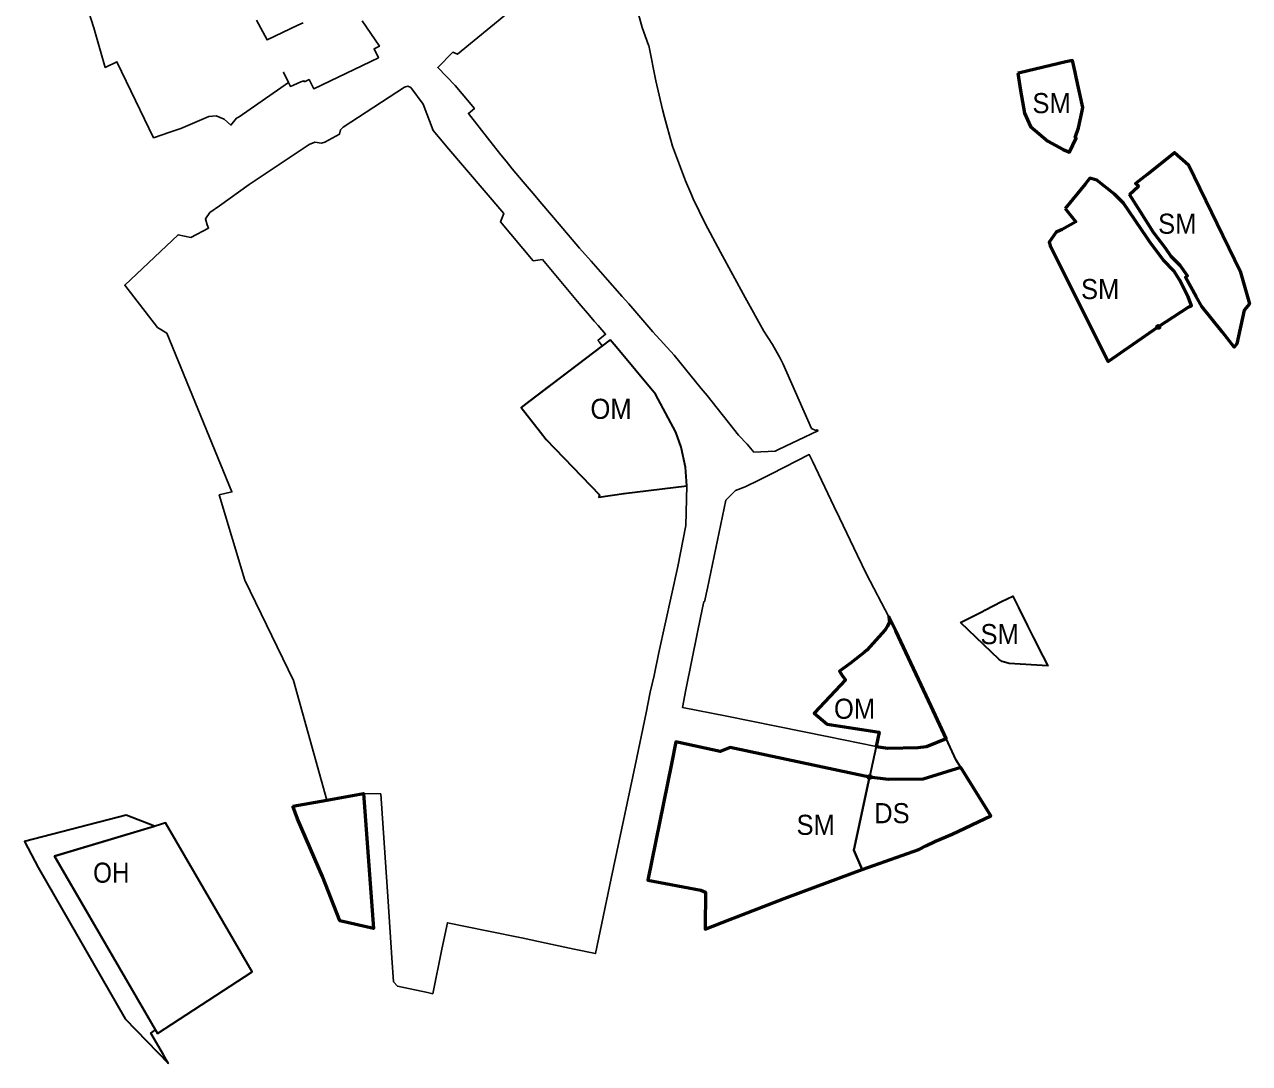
# Model space of a CAD drawing. Extents: x -650276 to -642489, y -1074311 to -1066720.
# Drawn here: x -647576 to -646845, y -1071614 to -1070993 of the extents above; entities that cross this region are included whole.
import ezdxf

# ---------------------------------------------------------------- set-up
doc = ezdxf.new("R2010")
doc.units = 0
doc.header["$LTSCALE"] = 4.8
doc.header["$PDMODE"] = 32
doc.header["$PDSIZE"] = 2.4
for name, color, linetype, lineweight in [('10', 7, 'Continuous', 35), ('12', 7, 'Continuous', 35), ('15', 7, 'Continuous', 35), ('18', 7, 'Continuous', 35), ('24', 7, 'Continuous', 35), ('60', 7, 'Continuous', 53), ('61', 7, 'Continuous', 25)]:
    doc.layers.add(name, color=color, linetype=linetype, lineweight=lineweight)
doc.layers.add('62', color=7, linetype='Continuous')

msp = doc.modelspace()

# ---------------------------------------------------------------- linework, layer by layer
at = {"layer": '10'}
msp.add_lwpolyline([(-647497.04, -1071595.66), (-647440.67, -1071558.93), (-647492.3, -1071470), (-647495.85, -1071471.06), (-647558.654, -1071489.738)], close=True, dxfattribs=at)
at = {"layer": '12'}
for points in [[(-647226.895, -1071181.511), (-647280.14, -1071221.92), (-647268.52, -1071236.78), (-647265.15, -1071241.1), (-647233.34, -1071274.07), (-647233.64, -1071275.42), (-647218.75, -1071273.32), (-647181.12, -1071268.66), (-647181.99, -1071257.66), (-647184.58, -1071245.67), (-647187.68, -1071236.74), (-647192.29, -1071228.1), (-647199.82, -1071213.98), (-647223.46, -1071185.83)], [(-647056.48, -1071355.32), (-647060.6, -1071346.87), (-647060.22, -1071349.87), (-647061.4, -1071352.51), (-647062.78, -1071354.77), (-647073.68, -1071366.75), (-647075.25, -1071368.01), (-647083.48, -1071374.62), (-647090.04, -1071379.44), (-647088.57, -1071381.97), (-647086.45, -1071384.59), (-647105.2, -1071404.54), (-647097.5, -1071410.96), (-647066.35, -1071415.79), (-647068.162, -1071424.298), (-647061.23, -1071425.434), (-647043.137, -1071424.978), (-647038.119, -1071424.37), (-647026.472, -1071419.614), (-647035.47, -1071400.31)]]:
    msp.add_lwpolyline(points, close=True, dxfattribs=at)
at = {"layer": '15'}
for points in [[(-647072.11, -1071442.6), (-647060.812, -1071444.006), (-647040.089, -1071443.76), (-647017.7, -1071436.79), (-647020.52, -1071432.42), (-647026.472, -1071419.614)], [(-647026.472, -1071419.614), (-647038.119, -1071424.37), (-647043.137, -1071424.978), (-647061.23, -1071425.434), (-647068.162, -1071424.298)], [(-647068.162, -1071424.298), (-647068.162, -1071424.298), (-647072.11, -1071442.6)], [(-647498.271, -1071593.544), (-647558.654, -1071489.738), (-647498.8, -1071471.94), (-647515.87, -1071465.25), (-647576.471, -1071481.091), (-647568.35, -1071496.656), (-647516.376, -1071586.89), (-647490.561, -1071613.609)], [(-647490.561, -1071613.609), (-647493.6, -1071608.5), (-647501.11, -1071595.45), (-647498.271, -1071593.544)]]:
    msp.add_lwpolyline(points, dxfattribs=at)
msp.add_point((-647072.11, -1071442.6), dxfattribs=at)
at = {"layer": '18'}
for points in [[(-646983.66, -1071022.3), (-646982.08, -1071032.76), (-646979.75, -1071046.19), (-646976.03, -1071054.29), (-646965.69, -1071063.05), (-646956.66, -1071067.91), (-646952.75, -1071069.62), (-646948.83, -1071061.12), (-646949.48, -1071060.79), (-646947.41, -1071054.95), (-646945.38, -1071045.82), (-646944.88, -1071042.78), (-646948.89, -1071024.84), (-646949.39, -1071021.83), (-646951.06, -1071014.78), (-646955.09, -1071015.67)], [(-646881.89, -1071077.03), (-646890.12, -1071069.67), (-646913.49, -1071088.22), (-646911.58, -1071089.9), (-646917.04, -1071094.75), (-646910.53, -1071105.18), (-646902.62, -1071117.58), (-646895.56, -1071126.84), (-646892.339, -1071131.481), (-646886.78, -1071137.25), (-646882.37, -1071143.39), (-646883.63, -1071144.15), (-646873.89, -1071161.58), (-646861.58, -1071177.05), (-646854.49, -1071185.87), (-646852.86, -1071183.98), (-646848.58, -1071163.95), (-646845.39, -1071159.98), (-646850.93, -1071140.54)], [(-646955.39, -1071103.23), (-646949.12, -1071111.22), (-646957.26, -1071115.61), (-646960.72, -1071117.25), (-646964.99, -1071123.18), (-646964.43, -1071125.3), (-646955.2, -1071143.67), (-646929.64, -1071194.58), (-646899.85, -1071173.89), (-646881.68, -1071161.83), (-646879.91, -1071161.24), (-646881.97, -1071155.84), (-646887.07, -1071145.66), (-646890.59, -1071140.39), (-646896.62, -1071133.93), (-646904.64, -1071123.54), (-646906.72, -1071120.46), (-646920.54, -1071099.98), (-646925.88, -1071094.68), (-646936.51, -1071086.33), (-646940.67, -1071085.15), (-646943.47, -1071088.69)], [(-647017.93, -1071350.33), (-647013.15, -1071348.01), (-647004.02, -1071343.32), (-647003.37, -1071342.99), (-646993.38, -1071337.85), (-646986.69, -1071334.53), (-646983.33, -1071341.44), (-646977.95, -1071352.38), (-646974.28, -1071359.48), (-646968.63, -1071370.46), (-646965.74, -1071376.18), (-646988.77, -1071374.77), (-646992.95, -1071373.61), (-646994.85, -1071372.49)], [(-647072.11, -1071442.6), (-647155.36, -1071425), (-647161.2, -1071427.33), (-647185.99, -1071421.98), (-647187.85, -1071421.58), (-647190.4, -1071434.75), (-647204.42, -1071504.1), (-647172.74, -1071510.15), (-647170.01, -1071511.22), (-647170.18, -1071532.22), (-647170.23, -1071533.44), (-647155.58, -1071527.62), (-647151.28, -1071525.99), (-647123.17, -1071515.01), (-647104.47, -1071508.08), (-647076.46, -1071497.69), (-647081.488, -1071486.251)]]:
    msp.add_lwpolyline(points, close=True, dxfattribs=at)
msp.add_point((-646899.85, -1071173.89), dxfattribs=at)
at = {"layer": '24'}
msp.add_line((-647081.488, -1071486.251), (-647076.46, -1071497.69), dxfattribs=at)
for points in [[(-647017.7, -1071436.79), (-647040.089, -1071443.76), (-647060.812, -1071444.006), (-647072.11, -1071442.6), (-647081.488, -1071486.251)], [(-647076.46, -1071497.69), (-647042.78, -1071485.76), (-647022.81, -1071476.61), (-646999.77, -1071465.81), (-647017.7, -1071436.79)]]:
    msp.add_lwpolyline(points, dxfattribs=at)
at = {"layer": '60'}
for points in [[(-646983.66, -1071022.3), (-646982.08, -1071032.76), (-646979.75, -1071046.19), (-646976.03, -1071054.29), (-646965.69, -1071063.05), (-646956.66, -1071067.91), (-646952.75, -1071069.62), (-646948.83, -1071061.12), (-646949.48, -1071060.79), (-646947.41, -1071054.95), (-646945.38, -1071045.82), (-646944.88, -1071042.78), (-646948.89, -1071024.84), (-646949.39, -1071021.83), (-646951.06, -1071014.78), (-646955.09, -1071015.67), (-646982.41, -1071022.23)], [(-646917.04, -1071094.75), (-646911.58, -1071089.9), (-646913.49, -1071088.22), (-646906.17, -1071082.72), (-646890.12, -1071069.67), (-646881.89, -1071077.03), (-646850.93, -1071140.54), (-646845.39, -1071159.98), (-646848.58, -1071163.95), (-646852.86, -1071183.98), (-646854.49, -1071185.87), (-646861.58, -1071177.05), (-646873.89, -1071161.58), (-646877.226, -1071155.611), (-646883.63, -1071144.15), (-646882.37, -1071143.39), (-646886.78, -1071137.25), (-646892.11, -1071131.81), (-646895.56, -1071126.84), (-646902.62, -1071117.58), (-646910.53, -1071105.18)], [(-646955.39, -1071103.23), (-646949.12, -1071111.22), (-646957.26, -1071115.61), (-646960.72, -1071117.25), (-646964.99, -1071123.18), (-646964.43, -1071125.3), (-646955.2, -1071143.67), (-646929.64, -1071194.58), (-646899.85, -1071173.89), (-646881.68, -1071161.83), (-646879.91, -1071161.24), (-646881.97, -1071155.84), (-646887.07, -1071145.66), (-646890.59, -1071140.39), (-646896.62, -1071133.93), (-646904.64, -1071123.54), (-646906.72, -1071120.46), (-646920.54, -1071099.98), (-646925.88, -1071094.68), (-646936.51, -1071086.33), (-646940.67, -1071085.15), (-646943.47, -1071088.69)], [(-647056.48, -1071355.32), (-647060.6, -1071346.87), (-647060.22, -1071349.87), (-647061.4, -1071352.51), (-647062.78, -1071354.77), (-647073.68, -1071366.75), (-647075.25, -1071368.01), (-647083.48, -1071374.62), (-647090.04, -1071379.44), (-647088.57, -1071381.97), (-647086.45, -1071384.59), (-647105.2, -1071404.54), (-647097.5, -1071410.96), (-647066.35, -1071415.79), (-647068.162, -1071424.298), (-647061.23, -1071425.434), (-647043.137, -1071424.978), (-647038.119, -1071424.37), (-647026.472, -1071419.614), (-647035.47, -1071400.31)], [(-647072.11, -1071442.6), (-647155.36, -1071425), (-647161.2, -1071427.33), (-647185.99, -1071421.98), (-647187.85, -1071421.58), (-647190.4, -1071434.75), (-647204.42, -1071504.1), (-647172.74, -1071510.15), (-647170.01, -1071511.22), (-647170.18, -1071532.22), (-647170.23, -1071533.44), (-647155.58, -1071527.62), (-647151.28, -1071525.99), (-647123.17, -1071515.01), (-647104.47, -1071508.08), (-647076.46, -1071497.69), (-647042.78, -1071485.76), (-647038.62, -1071483.74), (-647033.09, -1071481.06), (-647032.73, -1071480.88), (-647022.81, -1071476.61), (-646999.77, -1071465.81), (-647017.7, -1071436.79), (-647040.089, -1071443.76), (-647060.812, -1071444.006)], [(-647416.42, -1071460.03), (-647396.02, -1071456.32), (-647374.2, -1071452.36), (-647368.26, -1071532.99), (-647388.29, -1071528.41), (-647398.64, -1071501.96), (-647413.54, -1071467.53)]]:
    msp.add_lwpolyline(points, close=True, dxfattribs=at)
at = {"layer": '61'}
for points in [[(-647374.95, -1070991.15), (-647364.66, -1071006.25), (-647367.88, -1071007.78), (-647365.21, -1071013.19), (-647403.85, -1071031.66), (-647406.65, -1071026.24), (-647409.36, -1071027.52), (-647409.68, -1071026.85), (-647411.52, -1071027.64), (-647415.84, -1071029.49), (-647417.76, -1071030.31), (-647418.88, -1071028.01), (-647421.89, -1071021.82), (-647418.88, -1071028.01), (-647448.32, -1071048.39), (-647449.88, -1071049.31), (-647453.32, -1071053.37), (-647457.4, -1071049.84), (-647462.03, -1071047.83), (-647466.48, -1071048.33), (-647483.08, -1071055.41), (-647489.7, -1071057.66), (-647499.39, -1071060.95), (-647510.18, -1071038.65), (-647521.36, -1071015.52), (-647528.27, -1071018.94), (-647535.19, -1070995.23), (-647539.38, -1070981.6)], [(-647210.97, -1070983.56), (-647207.77, -1070995.03), (-647204.055, -1071005.609), (-647203.96, -1071005.88), (-647199.63, -1071026.94), (-647195.64, -1071044.04), (-647194.61, -1071048.68), (-647192.72, -1071055.27), (-647189.68, -1071065.99), (-647181.99, -1071086.74), (-647178.11, -1071095.31), (-647177.46, -1071097.42), (-647170.18, -1071112.08), (-647161.13, -1071129.3), (-647146.28, -1071156.35), (-647135.21, -1071176.44), (-647130.1, -1071184.33), (-647125.44, -1071192.58), (-647123.7, -1071196.19), (-647106.7, -1071234.45), (-647104.17, -1071235.6), (-647103.31, -1071235.22), (-647102.97, -1071235.92), (-647126.477, -1071247.083), (-647128.45, -1071248.02), (-647141.14, -1071248.62), (-647145.16, -1071243.92), (-647150.32, -1071238.51), (-647169.11, -1071214.8), (-647172.63, -1071210.63), (-647188.68, -1071190.78), (-647201.42, -1071176.7), (-647215.86, -1071160.1), (-647219.82, -1071155.78), (-647229.97, -1071144.1), (-647231.32, -1071142.57), (-647238.29, -1071134.66), (-647245.31, -1071126.75), (-647257.41, -1071112.55), (-647267.64, -1071100.44), (-647272.93, -1071094.24), (-647278.77, -1071087.15), (-647285.53, -1071079.39), (-647289.1, -1071074.88), (-647292.21, -1071071.21), (-647298.74, -1071062.85), (-647311.58, -1071046.44), (-647308, -1071043.56), (-647319.46, -1071029.7), (-647329.84, -1071018.95), (-647320.83, -1071009.87), (-647317.99, -1071010.98), (-647278.2, -1070978.19)], [(-647438.05, -1070990.74), (-647431.74, -1071002.56), (-647413.35, -1070993.67), (-647410.26, -1070992.23)]]:
    msp.add_lwpolyline(points, dxfattribs=at)
for points in [[(-647181.79, -1071292.49), (-647186.6, -1071316.98), (-647197.87, -1071368.22), (-647200.76, -1071382.02), (-647202.98, -1071391.98), (-647205.52, -1071404.32), (-647212.07, -1071435.71), (-647226.296, -1071503.249), (-647235.71, -1071547.94), (-647248.51, -1071545.3), (-647265.23, -1071541.68), (-647278.94, -1071538.77), (-647300.51, -1071534.33), (-647324.04, -1071529.54), (-647327.31, -1071545.25), (-647332.86, -1071571.94), (-647335.88, -1071571.31), (-647353.95, -1071567.53), (-647356.2, -1071564.75), (-647357.15, -1071550.44), (-647359.38, -1071516.88), (-647363.86, -1071452.66), (-647374.2, -1071452.36), (-647396.02, -1071456.32), (-647410.56, -1071404.35), (-647415.97, -1071385.01), (-647445, -1071324.99), (-647460.28, -1071274.02), (-647452.69, -1071272.32), (-647491.56, -1071177.65), (-647497.03, -1071174.18), (-647516.65, -1071148.87), (-647484.84, -1071118.8), (-647477.3, -1071120.38), (-647466.6, -1071114.88), (-647467.47, -1071112.93), (-647468.47, -1071109.42), (-647465.83, -1071105.54), (-647460.06, -1071101.57), (-647442.36, -1071088.82), (-647406.52, -1071065.05), (-647403.15, -1071063.6), (-647399.31, -1071064.09), (-647397.17, -1071063.56), (-647390.72, -1071059.94), (-647388.51, -1071058.82), (-647387.82, -1071056.14), (-647386.3, -1071054.58), (-647349.67, -1071030.64), (-647347.66, -1071030.16), (-647345.94, -1071030.88), (-647338.47, -1071040.94), (-647332.55, -1071056.58), (-647326.18, -1071064.18), (-647324.46, -1071066.41), (-647290.44, -1071106.08), (-647292.31, -1071111.16), (-647272.8, -1071134.42), (-647267.4, -1071133.54), (-647245.43, -1071159.88), (-647239.35, -1071166.98), (-647236.41, -1071170.41), (-647234.12, -1071172.97), (-647229.71, -1071178.23), (-647234.22, -1071182.02), (-647233.57, -1071182.82), (-647231.69, -1071185.15), (-647262.35, -1071208.42), (-647263.8, -1071209.52), (-647278.04, -1071220.33), (-647280.14, -1071221.92), (-647268.52, -1071236.78), (-647265.15, -1071241.1), (-647233.34, -1071274.07), (-647233.64, -1071275.42), (-647209.66, -1071272.22), (-647181.12, -1071268.66)], [(-647093.11, -1071411.77), (-647066.35, -1071415.79), (-647068.162, -1071424.298), (-647097.427, -1071418.318), (-647157.231, -1071406.28), (-647183.816, -1071400.974), (-647181.75, -1071390.51), (-647174.73, -1071356.1), (-647173.24, -1071348.27), (-647170.96, -1071337.84), (-647170.63, -1071337.91), (-647168.91, -1071329.88), (-647157.83, -1071277.35), (-647152.09, -1071271.47), (-647146.3, -1071269.33), (-647137.84, -1071265.06), (-647130.76, -1071261.49), (-647108.16, -1071250.08), (-647106.233, -1071254.01), (-647093.39, -1071280.83), (-647090, -1071287.89), (-647079.25, -1071310.33), (-647073.98, -1071321.53), (-647060.6, -1071346.87), (-647060.22, -1071349.87), (-647061.4, -1071352.51), (-647062.78, -1071354.77), (-647073.68, -1071366.75), (-647075.25, -1071368.01), (-647083.48, -1071374.62), (-647083.48, -1071374.62), (-647090.04, -1071379.44), (-647086.45, -1071384.59), (-647105.2, -1071404.54), (-647097.5, -1071410.96)]]:
    msp.add_lwpolyline(points, close=True, dxfattribs=at)

# ---------------------------------------------------------------- texts
at = {"layer": '62'}
for s, width, p in [('SM', 0.95, (-646974.938, -1071046.245)), ('SM', 0.95, (-646899.938, -1071118.245)), ('SM', 0.95, (-646945.938, -1071157.245)), ('OM', 0.95, (-647238.703, -1071228.756)), ('SM', 0.95, (-647005.938, -1071363.245)), ('OM', 0.95, (-647093.38, -1071407.817)), ('SM', 0.95, (-647115.735, -1071477.109)), ('DS', 0.95, (-647069.386, -1071470.148)), ('OH', 0.9, (-647535.508, -1071505.684))]:
    msp.add_text(s, height=12, dxfattribs=dict(at, width=width)).set_placement(p)

doc.saveas('drawing.dxf')
